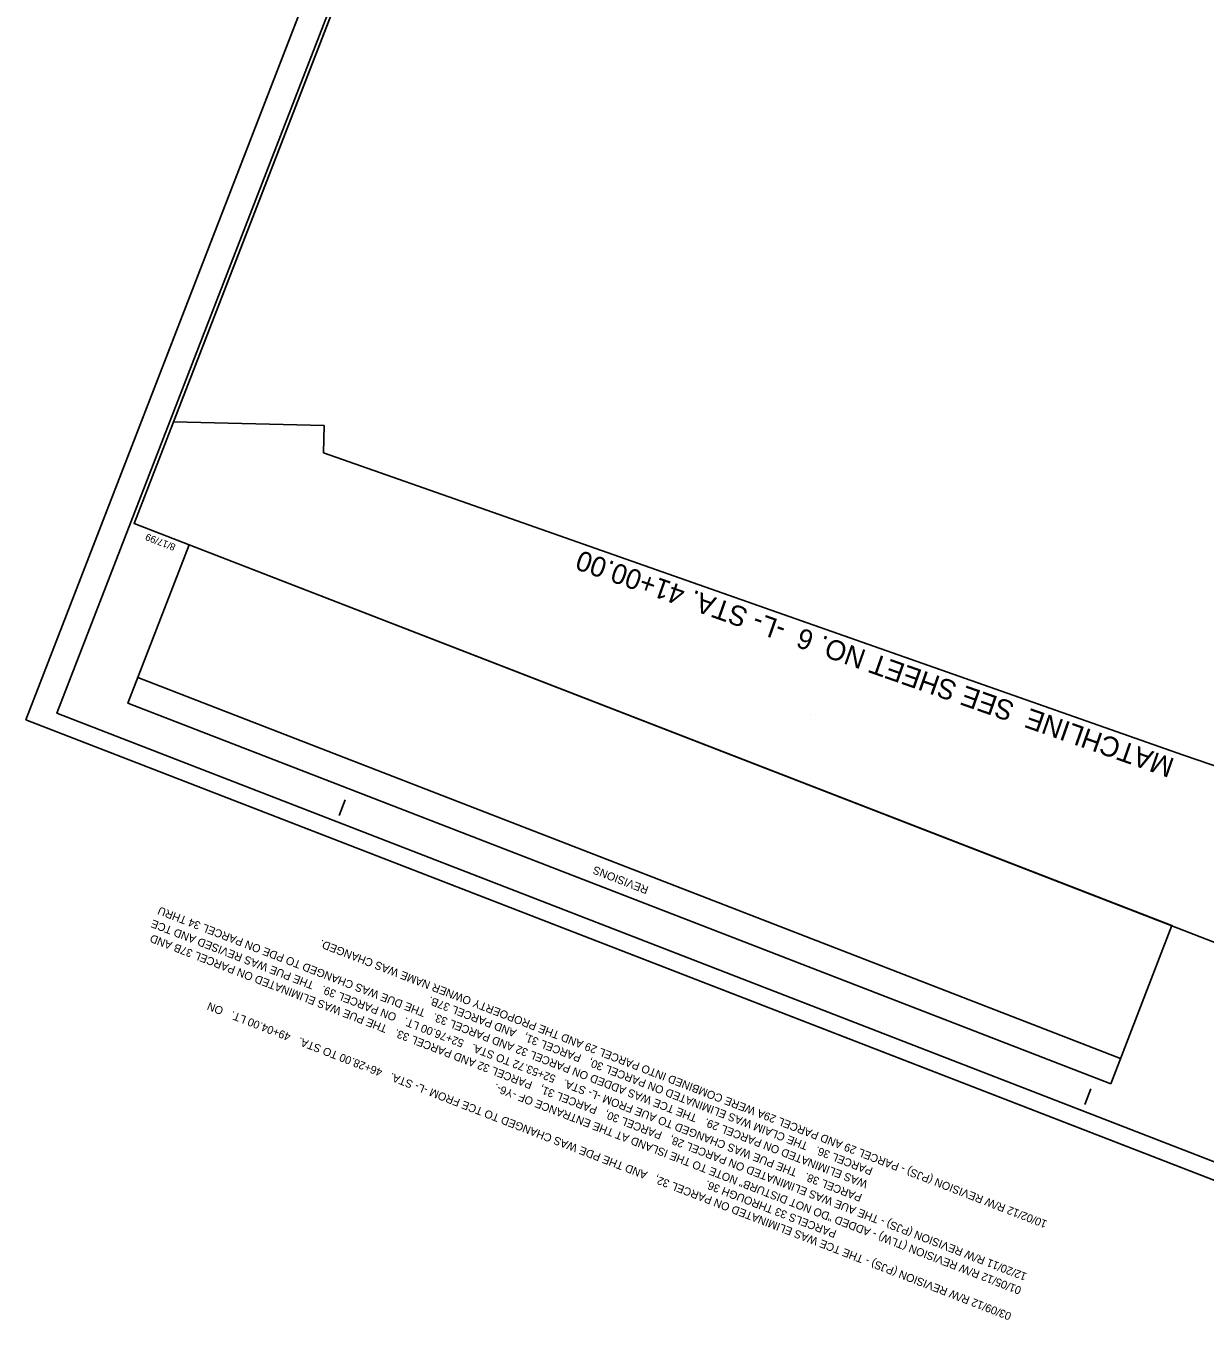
# Model space of a CAD drawing. Extents: x 1976816 to 1978446, y 780470 to 782626.
# Drawn here: x 1976816 to 1977701, y 780470 to 781441 of the extents above; entities that cross this region are included whole.
import ezdxf

# ---------------------------------------------------------------- set-up
doc = ezdxf.new("R2010")
doc.units = 0
for name, color, linetype in [('Matchline', 7, 'Continuous'), ('Matchline Text', 7, 'Continuous'), ('Sheet Block Revision CELL', 7, 'Continuous'), ('Sheet Clip Boundary CELL', 7, 'Continuous'), ('Sheet Cutting Line CELL', 7, 'Continuous'), ('Sheet Plan CELL', 7, 'Continuous'), ('Sheet Plan Layout CELL', 7, 'Continuous'), ('Sheet Plot Border Inside CELL', 7, 'Continuous'), ('Sheet Plot Border Outside CELL', 7, 'Continuous')]:
    doc.layers.add(name, color=color, linetype=linetype)

msp = doc.modelspace()

# ---------------------------------------------------------------- linework, layer by layer
at = {"layer": 'Matchline'}
msp.add_lwpolyline([(1977684.74, 780893.76), (1977425.18, 780985.03), (1977166.45, 781076.01)], dxfattribs=at)
at = {"layer": 'Sheet Block Revision CELL'}
msp.add_line((1977637.48, 780666.22), (1976900.25, 780951.86), dxfattribs=at)
msp.add_lwpolyline([(1977630.18, 780647.3), (1976892.84, 780932.64), (1976938.8, 781051.39), (1977676.13, 780766.05)], close=True, dxfattribs=at)
at = {"layer": 'Sheet Clip Boundary CELL'}
msp.add_lwpolyline([(1977924.48, 780811.85), (1978376.74, 781979.06), (1978142.45, 782069.81), (1977652.42, 782318.2), (1977659.93, 782314.31), (1977564.08, 782202.56), (1977366.88, 782278.97), (1977352.17, 782241), (1977411.94, 782200.15), (1977347.77, 782229.66), (1976926.95, 781143.58), (1977039.99, 781140.98), (1977039.7, 781120.49), (1977166.45, 781076.01), (1977684.74, 780893.76)], close=True, dxfattribs=at)
at = {"layer": 'Sheet Cutting Line CELL'}
for p, q in [((1977424.56, 782490.07), (1976816.32, 780920.29)), ((1976816.32, 780920.29), (1977837.35, 780524.67))]:
    msp.add_line(p, q, dxfattribs=at)
at = {"layer": 'Sheet Plan CELL'}
for p, q in [((1976897.44, 781067.4), (1976897.44, 781067.4)), ((1977405.04, 780924.35), (1977405.04, 780924.35)), ((1977051.28, 780848.54), (1977055.78, 780860.21)), ((1977610.75, 780631.79), (1977615.28, 780643.44))]:
    msp.add_line(p, q, dxfattribs=at)
for points in [[(1977439.39, 782466.12), (1976897.44, 781067.4), (1977876.51, 780688.04), (1978418.46, 782086.73)], [(1977876.51, 780688.04), (1976897.45, 781067.37), (1977367.09, 782279.56), (1977507.03, 782225.36), (1977579.31, 782411.88), (1978418.46, 782086.73)]]:
    msp.add_lwpolyline(points, close=True, dxfattribs=at)
at = {"layer": 'Sheet Plan Layout CELL'}
msp.add_lwpolyline([(1976897.45, 781067.37), (1977876.51, 780688.04), (1978418.45, 782086.72), (1977636.58, 782389.67), (1977550.14, 782166.58), (1977352.94, 782242.99)], close=True, dxfattribs=at)
at = {"layer": 'Sheet Plot Border Inside CELL'}
msp.add_lwpolyline([(1977823.4, 780544.02), (1978425.3, 782097.47), (1977441.58, 782478.65), (1976839.66, 780925.18)], close=True, dxfattribs=at)
at = {"layer": 'Sheet Plot Border Outside CELL'}
msp.add_lwpolyline([(1977837.35, 780524.67), (1978445.59, 782094.45), (1977424.56, 782490.07), (1976816.32, 780920.29)], close=True, dxfattribs=at)

# ---------------------------------------------------------------- texts
at = {"layer": 'Matchline Text'}
msp.add_text('MATCHLINE  SEE SHEET NO. 6  -L- STA. 41+00.00', height=15, rotation=160.62647, dxfattribs=at).set_placement((1977678.91, 780890.7))
at = {"layer": 'Sheet Block Revision CELL'}
for s, p in [('REVISIONS', (1977283.95, 780794.92)), ('WAS ELIMINATED ON PARCEL 29.   THE TCE WAS ADDED ON PARCEL 32 AND PARCEL 33.   THE DUE WAS CHANGED TO PDE ON PARCEL 34 THRU', (1977448.46, 780574.28)), ('PARCEL 38.   THE PUE WAS CHANGED TO AUE FROM -L- STA.   52+53.72 TO STA.   52+76.00 LT.   ON PARCEL 39.   THE PUE WAS REVISED AND TCE', (1977444.2, 780564.19)), ('12/20/11 R/W REVISION (PJS) - THE AUE WAS ELIMINATED ON PARCEL 28,   PARCEL 30,   PARCEL 31,   PARCEL 32 AND PARCEL 33.   THE PUE WAS ELIMINATED ON PARCEL 37B AND', (1977567.76, 780504.94)), ('10/02/12 R/W REVISION (PJS) - PARCEL 29 AND PARCEL 29A WERE COMBINED INTO PARCEL 29 AND THE PROPOERTY OWNER NAME WAS CHANGED.', (1977583.02, 780544.33)), ('03/09/12 R/W REVISION (PJS) - THE TCE WAS ELIMINATED ON PARCEL 32,   AND THE PDE WAS CHANGED TO TCE FROM -L- STA.   46+28.00 TO STA.   49+04.00 LT.   ON', (1977556.24, 780475.22)), ('PARCEL 36.   THE CLAIM WAS ELIMINATED ON PARCEL 30,   PARCEL 31,   AND PARCEL 37B.', (1977452.24, 780584.05)), ('01/05/12 R/W REVISION (TLW) - ADDED "DO NOT DISTURB" NOTE TO THE ISLAND AT THE ENTRANCE OF -Y6-.', (1977563.74, 780494.57)), ('PARCELS 33 THROUGH 36.', (1977425.01, 780536.98))]:
    msp.add_text(s, height=6, rotation=158.82032, dxfattribs=at).set_placement(p)
at = {"layer": 'Sheet Plan CELL'}
msp.add_text('8/17/99', height=5.25, rotation=158.82032, dxfattribs=at).set_placement((1976929.12, 781051.67))

doc.saveas('drawing.dxf')
